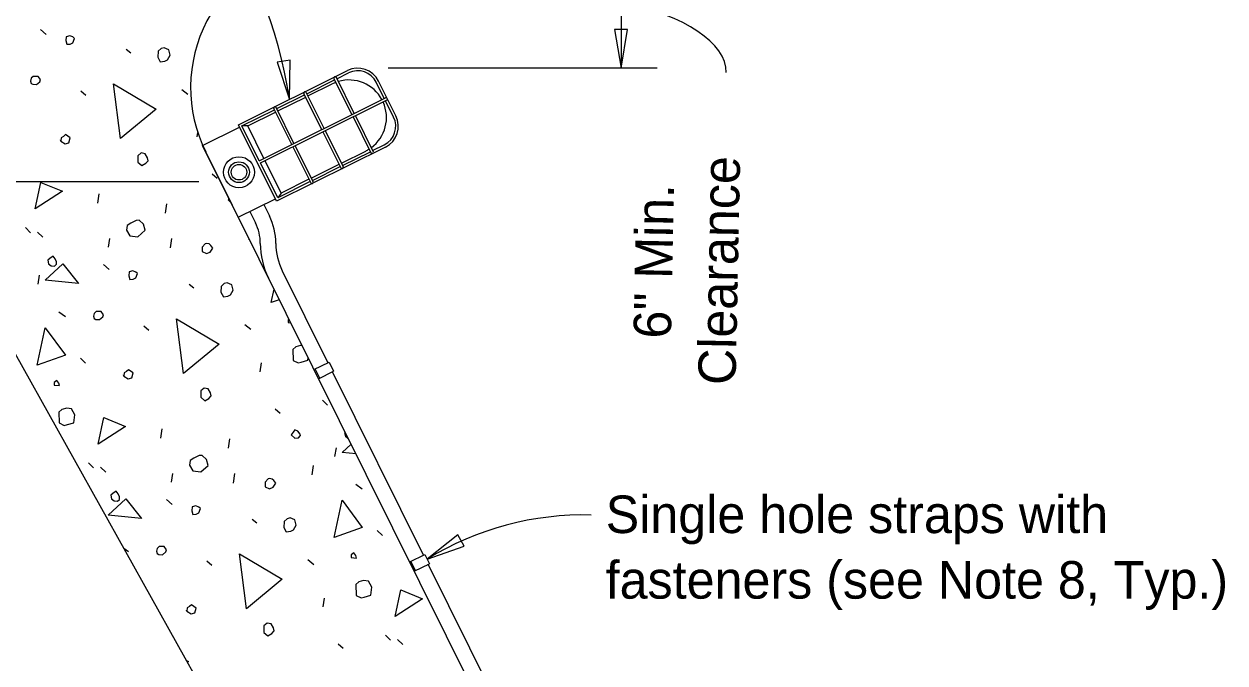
# Model space of a CAD drawing. Extents: x 112544 to 112597.1, y 111084 to 111107.1.
# Drawn here: x 112547.426 to 112552.261, y 111100.441 to 111103.015 of the extents above; entities that cross this region are included whole.
import ezdxf

# ---------------------------------------------------------------- set-up
doc = ezdxf.new("R2010")
doc.units = 0
for name, color, linetype in [('Dimension', 7, 'Continuous'), ('Lighting', 7, 'Continuous'), ('Miscellaneous', 7, 'Continuous'), ('SteelGirder', 7, 'Continuous'), ('SupstrConc', 7, 'Continuous')]:
    doc.layers.add(name, color=color, linetype=linetype)

msp = doc.modelspace()

# ---------------------------------------------------------------- linework, layer by layer
at = {"layer": 'Dimension'}
for p, q in [((112549.8296, 111103.3685), (112549.8296, 111102.8366)), ((112549.9754, 111102.8366), (112548.8921, 111102.8366)), ((112546.25, 111102.3807), (112548.1294, 111102.3807))]:
    msp.add_line(p, q, dxfattribs=at)
for points in [[(112549.8296, 111102.8365), (112549.856, 111102.9927), (112549.8031, 111102.9927)], [(112548.4946, 111102.7108), (112548.4969, 111102.8692), (112548.4446, 111102.8611)], [(112549.0486, 111100.8597), (112549.1983, 111100.9117), (112549.1728, 111100.9581)]]:
    msp.add_lwpolyline(points, close=True, dxfattribs=at)
for centre, major_axis, ratio, start_param, end_param in [((112547.7047, 111102.4058), (0.0174, -1.3204), 0.616683, 1.795781, 3.141615), ((112549.4704, 111102.8192), (-0.7827, 0), 0.407451, 3.141527, 4.235533), ((112549.6753, 111099.7249), (-0.0346, -1.3124), 0.953713, 3.141601, 3.693377)]:
    msp.add_ellipse(centre, major_axis=major_axis, ratio=ratio, start_param=start_param, end_param=end_param, dxfattribs=at)
at = {"layer": 'Lighting'}
for p, q in [((112548.2894, 111102.6088), (112548.7277, 111102.8268)), ((112548.5644, 111102.734), (112548.6764, 111102.7897)), ((112548.746, 111102.6498), (112548.6741, 111102.7943)), ((112548.7553, 111102.6544), (112548.6834, 111102.799)), ((112548.6857, 111102.7943), (112548.7324, 111102.8175)), ((112548.8765, 111102.7147), (112548.8441, 111102.78)), ((112548.923, 111102.6447), (112548.8534, 111102.7846)), ((112548.3729, 111102.4642), (112548.8812, 111102.717)), ((112548.3775, 111102.4549), (112548.8858, 111102.7077)), ((112548.4432, 111102.6737), (112548.5551, 111102.7294)), ((112548.6247, 111102.5895), (112548.5528, 111102.734)), ((112548.634, 111102.5941), (112548.5621, 111102.7387)), ((112548.9137, 111102.6401), (112548.8812, 111102.7054)), ((112548.3033, 111102.6041), (112548.4339, 111102.6691)), ((112548.5035, 111102.5292), (112548.4316, 111102.6737)), ((112548.5128, 111102.5338), (112548.4409, 111102.6783)), ((112548.7599, 111102.6451), (112548.8318, 111102.5005)), ((112548.1447, 111102.5253), (112548.294, 111102.5995)), ((112548.294, 111102.5995), (112548.2894, 111102.6088)), ((112548.4378, 111102.3104), (112548.294, 111102.5995)), ((112548.3729, 111102.4642), (112548.3033, 111102.6041)), ((112548.3266, 111102.6041), (112548.3033, 111102.6041)), ((112548.3915, 111102.4735), (112548.3266, 111102.6041)), ((112548.7506, 111102.6405), (112548.8225, 111102.4959)), ((112548.6293, 111102.5801), (112548.7012, 111102.4356)), ((112548.6387, 111102.5848), (112548.7105, 111102.4402)), ((112548.2885, 111102.2361), (112548.1447, 111102.5253)), ((112548.8808, 111102.5191), (112548.4424, 111102.3011)), ((112548.5081, 111102.5198), (112548.58, 111102.3753)), ((112548.5174, 111102.5245), (112548.5893, 111102.3799)), ((112548.7082, 111102.4449), (112548.8202, 111102.5005)), ((112548.8295, 111102.5052), (112548.8762, 111102.5284)), ((112548.4471, 111102.315), (112548.3775, 111102.4549)), ((112548.4611, 111102.3336), (112548.3961, 111102.4642)), ((112548.587, 111102.3846), (112548.6989, 111102.4402)), ((112548.5777, 111102.3799), (112548.4471, 111102.315)), ((112548.2885, 111102.2361), (112548.4378, 111102.3104)), ((112548.4424, 111102.3011), (112548.4378, 111102.3104)), ((112548.4611, 111102.3336), (112548.4471, 111102.315)), ((112548.3352, 111102.2593), (112548.3576, 111102.2143)), ((112548.3911, 111102.2872), (112548.4136, 111102.2421)), ((112548.6493, 111101.6511), (112548.4659, 111102.0199)), ((112549.0347, 111100.8762), (112548.6678, 111101.6138)), ((112549.4392, 111100.0628), (112549.0532, 111100.8388))]:
    msp.add_line(p, q, dxfattribs=at)
for radius in [0.0625, 0.0417, 0.0312]:
    msp.add_circle((112548.2913, 111102.4178), radius, dxfattribs=at)
for centre, radius, start, end in [((112548.6787, 111102.7966), 0.0052, 26.4422, 206.4423), ((112548.7695, 111102.7429), 0.0937, 26.4422, 116.4422), ((112548.7695, 111102.7429), 0.0833, 26.4422, 116.4422), ((112548.5575, 111102.7363), 0.0052, 26.4422, 206.4423), ((112548.8835, 111102.7124), 0.0052, 296.4087, 116.4422), ((112548.4362, 111102.676), 0.0052, 26.4422, 206.4423), ((112548.8391, 111102.603), 0.0937, 296.4422, 26.4422), ((112548.8391, 111102.603), 0.0833, 296.4422, 26.4422), ((112548.8271, 111102.4982), 0.0052, 206.4421, 26.4422), ((112548.7059, 111102.4379), 0.0052, 206.4421, 26.4422), ((112548.5846, 111102.3776), 0.0052, 206.4421, 26.4422), ((112548.1897, 111102.1308), 0.1875, 0.0537, 26.4422), ((112548.1897, 111102.1308), 0.25, 0.0537, 26.4422), ((112548.6897, 111102.1312), 0.3125, 180.0537, 206.4422), ((112548.6897, 111102.1312), 0.25, 180.0537, 206.2933)]:
    msp.add_arc(centre, radius, start, end, dxfattribs=at)
at = {"layer": 'Miscellaneous'}
for p, q in [((112547.4921, 111102.9924), (112547.5155, 111102.9728)), ((112547.8367, 111102.9139), (112547.8564, 111102.8985)), ((112547.654, 111102.7459), (112547.6743, 111102.728)), ((112548.0614, 111102.7515), (112548.0848, 111102.7319)), ((112548.5691, 111102.7247), (112548.6671, 111102.7734)), ((112548.4478, 111102.6644), (112548.5598, 111102.7201)), ((112548.3266, 111102.6041), (112548.4385, 111102.6597)), ((112548.1228, 111102.5609), (112548.1256, 111102.5774)), ((112548.7036, 111102.4542), (112548.8016, 111102.5029)), ((112548.1835, 111102.4116), (112548.2038, 111102.3937)), ((112548.5823, 111102.3939), (112548.6943, 111102.4496)), ((112548.573, 111102.3893), (112548.4611, 111102.3336)), ((112547.7234, 111102.2935), (112547.7289, 111102.3312)), ((112547.9958, 111102.2526), (112548.0012, 111102.2903)), ((112547.4316, 111102.1946), (112547.4525, 111102.1743)), ((112547.4804, 111102.1766), (112547.5014, 111102.1563)), ((112547.7658, 111102.1159), (112547.7719, 111102.1512)), ((112548.0151, 111102.1128), (112548.0206, 111102.1505)), ((112548.3323, 111102.146), (112548.3326, 111102.1476)), ((112547.7458, 111102.0458), (112547.7692, 111102.0262)), ((112547.4821, 111101.9674), (112547.4882, 111102.0027)), ((112548.0903, 111101.9673), (112548.11, 111101.9519)), ((112547.5665, 111101.8554), (112547.5922, 111101.8364)), ((112547.9076, 111101.7993), (112547.9279, 111101.7814)), ((112548.315, 111101.8049), (112548.3384, 111101.7853)), ((112547.6527, 111101.6689), (112547.6736, 111101.6486)), ((112548.3764, 111101.6143), (112548.3825, 111101.6496)), ((112548.627, 111101.5003), (112548.648, 111101.48)), ((112548.4372, 111101.465), (112548.4575, 111101.4471)), ((112547.9771, 111101.3469), (112547.9825, 111101.3845)), ((112548.2494, 111101.306), (112548.2549, 111101.3436)), ((112548.6775, 111101.2731), (112548.6836, 111101.3084)), ((112547.6852, 111101.248), (112547.7062, 111101.2277)), ((112547.734, 111101.23), (112547.755, 111101.2097)), ((112548.0195, 111101.1693), (112548.0256, 111101.2046)), ((112548.2688, 111101.1662), (112548.2742, 111101.2039)), ((112548.586, 111101.1994), (112548.5914, 111101.2371)), ((112548.7619, 111101.1612), (112548.7877, 111101.1422)), ((112547.9994, 111101.0992), (112548.0228, 111101.0796)), ((112548.344, 111101.0207), (112548.3636, 111101.0053)), ((112548.8481, 111100.9746), (112548.8691, 111100.9543)), ((112547.8277, 111100.9032), (112547.8459, 111100.8898)), ((112548.5687, 111100.8583), (112548.592, 111100.8387)), ((112548.1612, 111100.8527), (112548.1816, 111100.8348)), ((112548.6301, 111100.6677), (112548.6362, 111100.703)), ((112548.6908, 111100.5184), (112548.7111, 111100.5005)), ((112548.8806, 111100.5537), (112548.9016, 111100.5334)), ((112548.9295, 111100.5357), (112548.9504, 111100.5154))]:
    msp.add_line(p, q, dxfattribs=at)
for points in [[(112547.5948, 111102.9475), (112547.5987, 111102.933), (112547.6114, 111102.9338), (112547.6228, 111102.9394), (112547.6286, 111102.9565), (112547.6218, 111102.9625), (112547.6102, 111102.9671), (112547.5957, 111102.9632), (112547.5948, 111102.9475)], [(112547.966, 111102.9046), (112547.9646, 111102.8809), (112547.9746, 111102.8629), (112547.9922, 111102.865), (112548.0036, 111102.8706), (112548.0142, 111102.889), (112548.0084, 111102.9107), (112547.9906, 111102.9189), (112547.9786, 111102.9157), (112547.966, 111102.9046)], [(112547.4546, 111102.7753), (112547.4607, 111102.7718), (112547.4765, 111102.7708), (112547.489, 111102.7819), (112547.4919, 111102.7905), (112547.4832, 111102.8037), (112547.4626, 111102.8033), (112547.4542, 111102.7959), (112547.452, 111102.785), (112547.4546, 111102.7753)], [(112547.8143, 111102.5533), (112547.7863, 111102.7736), (112547.9584, 111102.6722), (112547.8143, 111102.5533)], [(112547.5737, 111102.5432), (112547.5921, 111102.5326), (112547.6065, 111102.5365), (112547.6117, 111102.556), (112547.5927, 111102.569), (112547.5843, 111102.5616), (112547.5753, 111102.5566), (112547.5737, 111102.5432), (112547.5724, 111102.548)], [(112547.8841, 111102.4763), (112547.8838, 111102.4581), (112547.9004, 111102.4444), (112547.916, 111102.4538), (112547.9261, 111102.4642), (112547.9229, 111102.4763), (112547.9135, 111102.4919), (112547.8971, 111102.4953), (112547.8846, 111102.4842), (112547.8841, 111102.4763)], [(112547.4709, 111102.2698), (112547.494, 111102.3769), (112547.5813, 111102.3408), (112547.4709, 111102.2698)], [(112548.2511, 111102.3114), (112548.2478, 111102.3071)], [(112548.2478, 111102.3071), (112548.2587, 111102.2961)], [(112547.8381, 111102.1844), (112547.8518, 111102.1622), (112547.884, 111102.1579), (112547.9133, 111102.1839), (112547.9068, 111102.208), (112547.8895, 111102.2241), (112547.8768, 111102.2233), (112547.8564, 111102.2126), (112547.8408, 111102.2033), (112547.8381, 111102.1844)], [(112548.1436, 111102.1162), (112548.1433, 111102.098), (112548.1611, 111102.0898), (112548.1749, 111102.0961), (112548.1861, 111102.112), (112548.1781, 111102.1228), (112548.1713, 111102.1288), (112548.1604, 111102.131), (112548.1555, 111102.1297), (112548.1436, 111102.1162)], [(112547.525, 111102.0488), (112547.5348, 111102.0411), (112547.5482, 111102.0395), (112547.5566, 111102.0469), (112547.5564, 111102.0572), (112547.5507, 111102.0686), (112547.5427, 111102.0794), (112547.5295, 111102.0707), (112547.5211, 111102.0633), (112547.525, 111102.0488)], [(112547.5115, 111101.983), (112547.582, 111102.0485), (112547.6446, 111101.9695), (112547.5115, 111101.983)], [(112547.8484, 111102.0008), (112547.8523, 111101.9864), (112547.865, 111101.9872), (112547.8765, 111101.9928), (112547.8822, 111102.0099), (112547.8755, 111102.0159), (112547.8639, 111102.0205), (112547.8494, 111102.0166), (112547.8484, 111102.0008)], [(112548.2197, 111101.958), (112548.2182, 111101.9343), (112548.2283, 111101.9163), (112548.2458, 111101.9184), (112548.2572, 111101.924), (112548.2678, 111101.9424), (112548.262, 111101.9641), (112548.2443, 111101.9723), (112548.2322, 111101.9691), (112548.2197, 111101.958)], [(112548.4209, 111101.8928), (112548.4324, 111101.9469)], [(112548.4534, 111101.9045), (112548.4209, 111101.8928)], [(112547.7082, 111101.8287), (112547.7143, 111101.8252), (112547.7301, 111101.8242), (112547.7427, 111101.8353), (112547.7455, 111101.8439), (112547.7368, 111101.8571), (112547.7162, 111101.8567), (112547.7079, 111101.8493), (112547.7056, 111101.8383), (112547.7082, 111101.8287)], [(112548.0679, 111101.6067), (112548.0399, 111101.827), (112548.2121, 111101.7256), (112548.0679, 111101.6067)], [(112548.4926, 111101.8259), (112548.4888, 111101.823), (112548.4889, 111101.8127)], [(112547.4791, 111101.6405), (112547.5111, 111101.7914), (112547.5924, 111101.6812), (112547.4791, 111101.6405)], [(112548.4889, 111101.8127), (112548.4996, 111101.8117)], [(112548.5455, 111101.7193), (112548.5396, 111101.7202), (112548.5203, 111101.715), (112548.5077, 111101.7039)], [(112548.5077, 111101.7039), (112548.5091, 111101.6602), (112548.5299, 111101.6503), (112548.5419, 111101.6535), (112548.5685, 111101.6606), (112548.5698, 111101.6705)], [(112547.8273, 111101.5966), (112547.8457, 111101.586), (112547.8602, 111101.5899), (112547.8653, 111101.6094), (112547.8463, 111101.6224), (112547.8379, 111101.615), (112547.8289, 111101.61), (112547.8273, 111101.5966), (112547.826, 111101.6014)], [(112547.5472, 111101.5604), (112547.5684, 111101.5583), (112547.5658, 111101.568), (112547.5578, 111101.5787), (112547.547, 111101.5707), (112547.5472, 111101.5604)], [(112548.1377, 111101.5297), (112548.1374, 111101.5115), (112548.154, 111101.4978), (112548.1696, 111101.5072), (112548.1798, 111101.5176), (112548.1765, 111101.5297), (112548.1672, 111101.5453), (112548.1507, 111101.5487), (112548.1382, 111101.5376), (112548.1377, 111101.5297)], [(112547.566, 111101.4515), (112547.5673, 111101.4079), (112547.5881, 111101.3979), (112547.6002, 111101.4012), (112547.6267, 111101.4083), (112547.631, 111101.4405), (112547.6167, 111101.4651), (112547.5978, 111101.4678), (112547.5785, 111101.4626), (112547.566, 111101.4515)], [(112547.7246, 111101.3232), (112547.7476, 111101.4303), (112547.835, 111101.3942), (112547.7246, 111101.3232)], [(112548.5014, 111101.3605), (112548.5156, 111101.3462), (112548.5307, 111101.3477), (112548.5384, 111101.3575), (112548.5371, 111101.3623), (112548.5284, 111101.3755), (112548.5168, 111101.3802), (112548.5091, 111101.3704), (112548.5014, 111101.3605)], [(112548.7188, 111101.371), (112548.7165, 111101.369), (112548.7204, 111101.3545)], [(112548.7204, 111101.3545), (112548.7302, 111101.3468), (112548.7309, 111101.3467)], [(112548.707, 111101.2888), (112548.743, 111101.3223)], [(112548.0917, 111101.2378), (112548.1054, 111101.2156), (112548.1376, 111101.2113), (112548.1669, 111101.2373), (112548.1604, 111101.2614), (112548.1432, 111101.2775), (112548.1305, 111101.2767), (112548.11, 111101.266), (112548.0944, 111101.2567), (112548.0917, 111101.2378)], [(112548.7625, 111101.2831), (112548.707, 111101.2888)], [(112548.3973, 111101.1696), (112548.397, 111101.1514), (112548.4147, 111101.1432), (112548.4285, 111101.1495), (112548.4398, 111101.1654), (112548.4317, 111101.1762), (112548.425, 111101.1822), (112548.414, 111101.1844), (112548.4092, 111101.1831), (112548.3973, 111101.1696)], [(112547.7652, 111101.0364), (112547.8356, 111101.1019), (112547.8982, 111101.0229), (112547.7652, 111101.0364)], [(112547.7786, 111101.1022), (112547.7885, 111101.0944), (112547.8018, 111101.0928), (112547.8102, 111101.1003), (112547.81, 111101.1106), (112547.8044, 111101.122), (112547.7963, 111101.1328), (112547.7831, 111101.1241), (112547.7748, 111101.1166), (112547.7786, 111101.1022)], [(112548.6745, 111100.9462), (112548.7066, 111101.0972), (112548.7878, 111100.9869), (112548.6745, 111100.9462)], [(112548.1021, 111101.0542), (112548.1059, 111101.0397), (112548.1187, 111101.0406), (112548.1301, 111101.0462), (112548.1359, 111101.0633), (112548.1291, 111101.0692), (112548.1175, 111101.0739), (112548.103, 111101.07), (112548.1021, 111101.0542)], [(112548.4733, 111101.0114), (112548.4719, 111100.9877), (112548.4819, 111100.9697), (112548.4994, 111100.9718), (112548.5109, 111100.9774), (112548.5215, 111100.9958), (112548.5157, 111101.0175), (112548.4979, 111101.0257), (112548.4859, 111101.0225), (112548.4733, 111101.0114)], [(112547.9618, 111100.8821), (112547.968, 111100.8785), (112547.9838, 111100.8776), (112547.9963, 111100.8887), (112547.9992, 111100.8973), (112547.9905, 111100.9105), (112547.9699, 111100.9101), (112547.9615, 111100.9027), (112547.9593, 111100.8917), (112547.9618, 111100.8821)], [(112548.3215, 111100.6601), (112548.2936, 111100.8804), (112548.4657, 111100.779), (112548.3215, 111100.6601)], [(112548.7426, 111100.8661), (112548.7638, 111100.864), (112548.7613, 111100.8737), (112548.7532, 111100.8845), (112548.7424, 111100.8764), (112548.7426, 111100.8661)], [(112548.7614, 111100.7573), (112548.7627, 111100.7136), (112548.7835, 111100.7037), (112548.7956, 111100.7069), (112548.8222, 111100.714), (112548.8265, 111100.7462), (112548.8121, 111100.7709), (112548.7933, 111100.7736), (112548.7739, 111100.7684), (112548.7614, 111100.7573)], [(112548.92, 111100.6289), (112548.9431, 111100.7361), (112549.0304, 111100.6999), (112548.92, 111100.6289)], [(112548.081, 111100.65), (112548.0993, 111100.6394), (112548.1138, 111100.6433), (112548.119, 111100.6628), (112548.0999, 111100.6758), (112548.0916, 111100.6684), (112548.0826, 111100.6634), (112548.081, 111100.65), (112548.0797, 111100.6548)], [(112548.3914, 111100.5831), (112548.3911, 111100.5649), (112548.4077, 111100.5512), (112548.4233, 111100.5606), (112548.4334, 111100.571), (112548.4302, 111100.5831), (112548.4208, 111100.5987), (112548.4044, 111100.6021), (112548.3918, 111100.591), (112548.3914, 111100.5831)], [(112548.08, 111100.4512), (112548.0886, 111100.4476), (112548.0837, 111100.4444)]]:
    msp.add_lwpolyline(points, dxfattribs=at)
for start, end in [(110.5219, 116.4422), (28.4157, 106.5369), (306.3475, 24.4687), (296.4422, 302.3625)]:
    msp.add_arc((112548.7343, 111102.6382), 0.151, start, end, dxfattribs=at)
at = {"layer": 'SteelGirder'}
for p, q in [((112548.5933, 111101.6233), (112548.6539, 111101.6534)), ((112548.6539, 111101.6534), (112548.6725, 111101.6161)), ((112548.6165, 111101.5882), (112548.598, 111101.6256)), ((112548.6119, 111101.5859), (112548.6725, 111101.6161)), ((112548.9787, 111100.8483), (112549.0393, 111100.8785)), ((112549.0393, 111100.8785), (112549.0579, 111100.8411)), ((112549.0019, 111100.8133), (112548.9834, 111100.8506)), ((112548.9973, 111100.811), (112549.0579, 111100.8411))]:
    msp.add_line(p, q, dxfattribs=at)
at = {"layer": 'SupstrConc'}
for p, q in [((112549.7499, 111099.2976), (112548.1577, 111102.4992)), ((112550.511, 111096.0946), (112547.0612, 111102.2767))]:
    msp.add_line(p, q, dxfattribs=at)
msp.add_arc((112548.68, 111102.759), 0.5833, 98.8325, 206.4422, dxfattribs=at)

# ---------------------------------------------------------------- texts
at = {"layer": 'Dimension'}
for s, p in [('Clearance', (112550.2908, 111101.5597)), ('6" Min.', (112550.0305, 111101.7468))]:
    msp.add_text(s, height=0.1512, rotation=88.8542, dxfattribs=at).set_placement(p)
for s, p in [('Single hole straps with', (112549.7678, 111100.9646)), ('fasteners (see Note 8, Typ.)', (112549.7678, 111100.7006))]:
    msp.add_text(s, height=0.1512, dxfattribs=at).set_placement(p)

doc.saveas('drawing.dxf')
